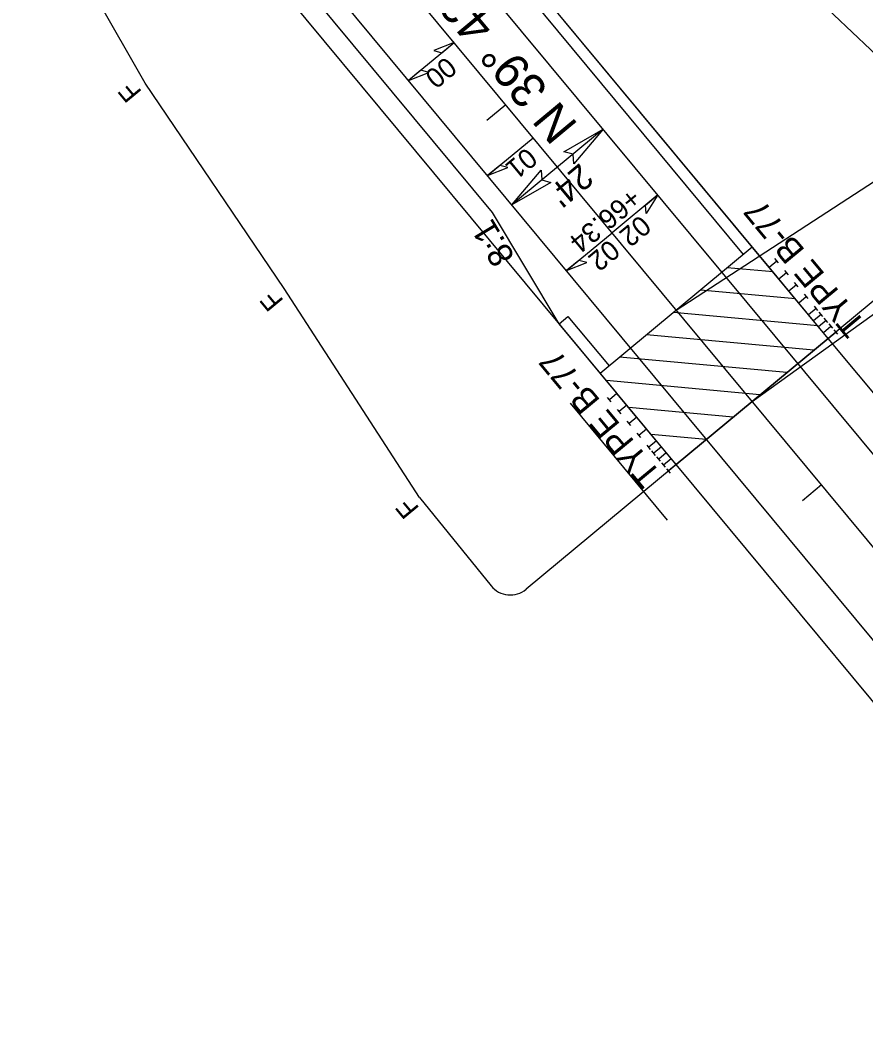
# Model space of a CAD drawing. Extents: x 2597570 to 2598622, y 852675 to 853890.
# Drawn here: x 2597851 to 2598022, y 853191.7 to 853396.2 of the extents above; entities that cross this region are included whole.
import ezdxf

# ---------------------------------------------------------------- set-up
doc = ezdxf.new("R2010")
doc.units = 0
for name, color, linetype in [('Exist Hydrographic Channel Edge', 7, 'Continuous'), ('Exist Plan Preparation Drainage Arrows Symbol CELL', 7, 'Continuous'), ('Exist Structure Major Deck Tunnel Box Culvert', 7, 'Continuous'), ('Prop Drainage Structure Box Number Symbol CELL', 7, 'Continuous'), ('Prop Drainage Structure Drop Inlet Grate 2 Narrow Slots and Flat Grates 840 29 CELL', 7, 'Continuous'), ('Prop Drainage Structure Drop Inlet Grate 2 Narrow Slots and Flat Grates 840 29 Label', 7, 'Continuous'), ('Prop Drainage Structure Drop Inlet Grate 2 Narrow Slots and Flat Grates 840 29 TB CELL', 7, 'Continuous'), ('Prop Drainage Structure Gutter Shoulder Berm Label', 7, 'Continuous'), ('Prop Drainage Structure Pipe RCP 15in Class IV', 7, 'Continuous'), ('Prop Drainage Structure Pipe RCP 15in Class IV Label', 7, 'Continuous'), ('Prop Drainage Structure Plot Symbol 20 Scale', 7, 'Continuous'), ('Prop Drainage Structure Plot Symbol 50 Scale', 7, 'Continuous'), ('Prop Earthen Structure Base Ditch Berm Detail Label', 7, 'Continuous'), ('Prop Earthen Structure Ditch Flow Line', 7, 'Continuous'), ('Prop Earthen Structure V Ditch Lateral Detail CELL', 7, 'Continuous'), ('Prop Earthen Structure V Ditch Special Lateral Detail CELL', 7, 'Continuous'), ('Prop Erosion Rip Rap Pad at Outlet CELL', 7, 'Continuous'), ('Prop Erosion Rip Rap Pad at Outlet Label', 7, 'Continuous'), ('Prop Plan Preparation Sketches Hydraulic Ditch', 7, 'Continuous'), ('Scratch_Level_3', 7, 'Continuous')]:
    doc.layers.add(name, color=color, linetype=linetype)

msp = doc.modelspace()

# ---------------------------------------------------------------- linework, layer by layer
at = {"layer": 'Exist Hydrographic Channel Edge'}
msp.add_line((2598276.51, 852984.93), (2597890.84, 853449.35), dxfattribs=at)
msp.add_line((2598276.51, 852984.93), (2597890.84, 853449.35), dxfattribs=at)
at = {"layer": 'Exist Plan Preparation Drainage Arrows Symbol CELL'}
for p, q in [((2597949.2, 853379.08), (2597945.35, 853375.89)), ((2598013.09, 853302.15), (2598009.24, 853298.95))]:
    msp.add_line(p, q, dxfattribs=at)
at = {"layer": 'Prop Drainage Structure Box Number Symbol CELL'}
for points in [[(2597960.98, 853369.59), (2597968.89, 853374.15), (2597962.95, 853367.14), (2597962.81, 853369.1)], [(2597958.34, 853363.38), (2597950.43, 853358.82), (2597956.37, 853365.83), (2597956.5, 853363.87)]]:
    msp.add_lwpolyline(points, close=True, dxfattribs=at)
at = {"layer": 'Prop Drainage Structure Drop Inlet Grate 2 Narrow Slots and Flat Grates 840 29 CELL'}
for p, q in [((2598002.47, 853346.24), (2598004.01, 853347.51)), ((2598004.38, 853347.07), (2598003.64, 853347.95)), ((2598014.45, 853331.81), (2598002.47, 853346.24)), ((2598004.47, 853343.83), (2598006.01, 853345.11)), ((2598006.37, 853344.67), (2598005.64, 853345.55)), ((2598006.46, 853341.43), (2598008, 853342.71)), ((2598008.37, 853342.26), (2598007.64, 853343.15)), ((2598008.46, 853339.02), (2598010, 853340.3)), ((2598010.36, 853339.86), (2598009.63, 853340.74)), ((2598012.36, 853337.46), (2598011.63, 853338.34)), ((2598010.46, 853336.62), (2598012, 853337.9)), ((2598011.45, 853335.42), (2598012.99, 853336.69)), ((2598013.36, 853336.25), (2598012.63, 853337.14)), ((2598012.45, 853334.22), (2598013.99, 853335.49)), ((2598013.45, 853333.01), (2598014.99, 853334.29)), ((2598014.36, 853335.05), (2598013.63, 853335.93)), ((2598015.36, 853333.85), (2598014.62, 853334.73)), ((2598014.45, 853331.81), (2598015.99, 853333.09)), ((2598016.35, 853332.65), (2598015.62, 853333.53)), ((2597970.52, 853318.96), (2597969.79, 853319.84)), ((2597971.7, 853320.68), (2597970.16, 853319.4)), ((2597983.68, 853306.26), (2597971.7, 853320.68)), ((2597973.69, 853318.28), (2597972.16, 853317)), ((2597972.52, 853316.56), (2597971.79, 853317.44)), ((2597975.69, 853315.87), (2597974.15, 853314.6)), ((2597974.52, 853314.15), (2597973.79, 853315.04)), ((2597976.51, 853311.75), (2597975.78, 853312.63)), ((2597977.69, 853313.47), (2597976.15, 853312.19)), ((2597978.51, 853309.35), (2597977.78, 853310.23)), ((2597979.68, 853311.07), (2597978.14, 853309.79)), ((2597980.68, 853309.86), (2597979.14, 853308.59)), ((2597979.51, 853308.14), (2597978.78, 853309.03)), ((2597980.51, 853306.94), (2597979.78, 853307.82)), ((2597981.68, 853308.66), (2597980.14, 853307.38)), ((2597981.51, 853305.74), (2597980.77, 853306.62)), ((2597982.68, 853307.46), (2597981.14, 853306.18)), ((2597983.68, 853306.26), (2597982.14, 853304.98)), ((2597982.5, 853304.54), (2597981.77, 853305.42))]:
    msp.add_line(p, q, dxfattribs=at)
at = {"layer": 'Prop Drainage Structure Drop Inlet Grate 2 Narrow Slots and Flat Grates 840 29 Label'}
for points in [[(2597938.76, 853391.66), (2597934.63, 853390.05), (2597936.27, 853389.58)], [(2597929.53, 853383.98), (2597933.65, 853385.59), (2597932.02, 853386.06)], [(2597945.5, 853364.75), (2597949.62, 853366.36), (2597947.99, 853366.82)], [(2597979.94, 853360.85), (2597977.59, 853357.09), (2597977.44, 853358.79)], [(2597961.47, 853345.52), (2597965.59, 853347.14), (2597963.95, 853347.6)]]:
    msp.add_lwpolyline(points, close=True, dxfattribs=at)
at = {"layer": 'Prop Drainage Structure Drop Inlet Grate 2 Narrow Slots and Flat Grates 840 29 TB CELL'}
for p, q in [((2598014.45, 853331.81), (2597983.68, 853306.26)), ((2598084.72, 853247.19), (2598014.45, 853331.81)), ((2598053.95, 853221.63), (2597983.68, 853306.26))]:
    msp.add_line(p, q, dxfattribs=at)
at = {"layer": 'Prop Drainage Structure Gutter Shoulder Berm Label'}
msp.add_line((2597968.89, 853374.15), (2597950.43, 853358.82), dxfattribs=at)
at = {"layer": 'Prop Drainage Structure Pipe RCP 15in Class IV'}
for p, q in [((2597876.23, 853383.48), (2597850.98, 853427.78)), ((2598031.35, 853382.31), (2597994.87, 853417.01)), ((2597904.4, 853341.88), (2597876.23, 853383.48)), ((2598045.47, 853357.57), (2597953.3, 853281.03)), ((2597931.76, 853299.6), (2597904.4, 853341.88)), ((2597931.76, 853299.6), (2597946.22, 853281.73))]:
    msp.add_line(p, q, dxfattribs=at)
msp.add_arc((2597950.11, 853284.88), 5, 218.999, 309.7067, dxfattribs=at)
at = {"layer": 'Prop Drainage Structure Pipe RCP 15in Class IV Label'}
for p, q in [((2597983.7, 853337.54), (2598062.79, 853389.05)), ((2597999.06, 853319.03), (2598070.55, 853370.55))]:
    msp.add_line(p, q, dxfattribs=at)
at = {"layer": 'Prop Drainage Structure Plot Symbol 20 Scale'}
for p, q in [((2598285.74, 852992.6), (2597900.08, 853457.02)), ((2598267.28, 852977.26), (2597881.61, 853441.69))]:
    msp.add_line(p, q, dxfattribs=at)
at = {"layer": 'Prop Drainage Structure Plot Symbol 50 Scale'}
for p, q in [((2597946.51, 853357.27), (2597878.54, 853439.13)), ((2597997.3, 853348.81), (2597922.87, 853438.44)), ((2597959.99, 853334.78), (2597946.51, 853357.27)), ((2597959.99, 853334.78), (2597961.78, 853336.27)), ((2597961.78, 853336.27), (2597970.1, 853326.26))]:
    msp.add_line(p, q, dxfattribs=at)
at = {"layer": 'Prop Earthen Structure Ditch Flow Line'}
for p, q in [((2597938.76, 853391.65), (2597929.53, 853383.98)), ((2597945.5, 853364.75), (2597954.73, 853372.42)), ((2597979.94, 853360.85), (2597970.7, 853353.18)), ((2597961.47, 853345.52), (2597970.7, 853353.18))]:
    msp.add_line(p, q, dxfattribs=at)
at = {"layer": 'Prop Earthen Structure V Ditch Lateral Detail CELL'}
for p, q in [((2598003.29, 853345.25), (2597994, 853346.11)), ((2598007.81, 853339.81), (2597988.56, 853341.59)), ((2598012.33, 853334.37), (2597983.12, 853337.07)), ((2598011.51, 853329.42), (2597977.68, 853332.56)), ((2598006.06, 853324.9), (2597972.24, 853328.04)), ((2598000.62, 853320.39), (2597969.55, 853323.27)), ((2597995.17, 853315.87), (2597974.07, 853317.83)), ((2597989.72, 853311.35), (2597978.59, 853312.39))]:
    msp.add_line(p, q, dxfattribs=at)
at = {"layer": 'Prop Earthen Structure V Ditch Special Lateral Detail CELL'}
msp.add_line((2597962.22, 853318.68), (2597981.84, 853295.05), dxfattribs=at)
at = {"layer": 'Prop Erosion Rip Rap Pad at Outlet CELL'}
for p, q in [((2598002.47, 853346.24), (2597924.66, 853439.93)), ((2597885.25, 853424.79), (2597971.69, 853320.69)), ((2598014.45, 853331.81), (2598002.47, 853346.24)), ((2597983.67, 853306.27), (2597971.69, 853320.69))]:
    msp.add_line(p, q, dxfattribs=at)
at = {"layer": 'Prop Plan Preparation Sketches Hydraulic Ditch'}
for p, q in [((2598014.45, 853331.81), (2597924.66, 853439.93)), ((2597983.68, 853306.26), (2597959.99, 853334.78))]:
    msp.add_line(p, q, dxfattribs=at)
at = {"layer": 'Scratch_Level_3'}
for p, q in [((2597968.3, 853324.77), (2597999.07, 853350.33)), ((2598014.45, 853331.81), (2597999.07, 853350.33)), ((2597983.68, 853306.26), (2598014.45, 853331.81)), ((2597983.68, 853306.26), (2597968.3, 853324.77))]:
    msp.add_line(p, q, dxfattribs=at)

# ---------------------------------------------------------------- texts
at = {"layer": 'Exist Structure Major Deck Tunnel Box Culvert'}
msp.add_text('N 39%%d 42\' 24.1" W', height=7, rotation=129.7067, dxfattribs=at).set_placement((2597963.99, 853375.02))
at = {"layer": 'Prop Drainage Structure Drop Inlet Grate 2 Narrow Slots and Flat Grates 840 29 CELL'}
for p in [(2598022.24, 853334.75), (2597980.83, 853304.35)]:
    msp.add_text('TYPE B-77', height=5, rotation=129.7067, dxfattribs=at).set_placement(p)
at = {"layer": 'Prop Earthen Structure Base Ditch Berm Detail Label'}
for p in [(2597875.73, 853381.69), (2597904.42, 853339.43), (2597931.86, 853297.44)]:
    msp.add_text('F', height=4, rotation=129.7067, dxfattribs=at).set_placement(p)
at = {"layer": 'Prop Earthen Structure Ditch Flow Line'}
for s, rotation, p in [('00', 219.7067, (2597937.12, 853389)), ('01', 219.7067, (2597953.42, 853370.62)), ('+66.34', 219.5363, (2597974.49, 853362.43)), ('02', 219.7067, (2597976.43, 853356.95)), ('02', 219.7067, (2597970.13, 853352.01))]:
    msp.add_text(s, height=4, rotation=rotation, dxfattribs=at).set_placement(p)
at = {"layer": 'Prop Erosion Rip Rap Pad at Outlet Label'}
for s, rotation, p in [("24'", 219.7067, (2597964.23, 853367.45)), ('8:1', 120.9326, (2597951.16, 853348.32))]:
    msp.add_text(s, height=5, rotation=rotation, dxfattribs=at).set_placement(p)

doc.saveas('drawing.dxf')
